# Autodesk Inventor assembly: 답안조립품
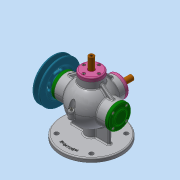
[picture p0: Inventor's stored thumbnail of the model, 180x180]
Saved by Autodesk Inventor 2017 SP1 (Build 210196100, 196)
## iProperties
Part Number: 답안조립품
Material: 일반
Document SubType Name: Assembly
Designer: MRC
Mass: 3721.38 g
Surface Area: 2584.17 cm^2
Volume: 938.795 cm^3
Density: 3.96399 g/cm^3
Author: MRC
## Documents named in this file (17)
- C:\Users\MRC\Desktop\620909V1006\답안조립품.iam
- C:\Users\MRC\Desktop\620909V1006\본체.ipt
- C:\Users\MRC\Desktop\620909V1006\V-벨트풀리.ipt
- C:\Users\MRC\Desktop\620909V1006\가변스프링1.ipt
- C:\Users\MRC\Desktop\620909V1006\가변스프링2.ipt
- C:\Users\MRC\Desktop\620909V1006\너트-M8x1.ipt
- C:\Users\MRC\Desktop\620909V1006\뒤커버.ipt
- C:\Users\MRC\Desktop\620909V1006\베어링- 6202.ipt
- C:\Users\MRC\Desktop\620909V1006\본체커버.ipt
- C:\Users\MRC\Desktop\620909V1006\볼트 M4x0.7.ipt
- C:\Users\MRC\Desktop\620909V1006\슬라이드 커버.ipt
- C:\Users\MRC\Desktop\620909V1006\슬라이드.ipt
- C:\Users\MRC\Desktop\620909V1006\앞커버.ipt
- C:\Users\MRC\Desktop\620909V1006\오일실.ipt
- C:\Users\MRC\Desktop\620909V1006\와셔 8x17.ipt
- C:\Users\MRC\Desktop\620909V1006\축.ipt
- C:\Users\MRC\Desktop\620909V1006\키-4x4.ipt
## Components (20 placed, 4 different names)
1. V-벨트풀리:1
2. 가변스프링1:1
3. 가변스프링2:1
4. M4x0.7x12:17
5. M4x0.7x12:2
6. M4x0.7x12:5
7. M4x0.7x12:6
8. M4x0.7x12:7
9. M4x0.7x12:1
10. M4x0.7x12:8
11. M4x0.7x12:9
12. M4x0.7x12:10
13. M4x0.7x12:4
14. M4x0.7x12:11
15. M4x0.7x12:12
16. M4x0.7x12:13
17. M4x0.7x12:3
18. M4x0.7x12:14
19. M4x0.7x12:15
20. M4x0.7x12:16
